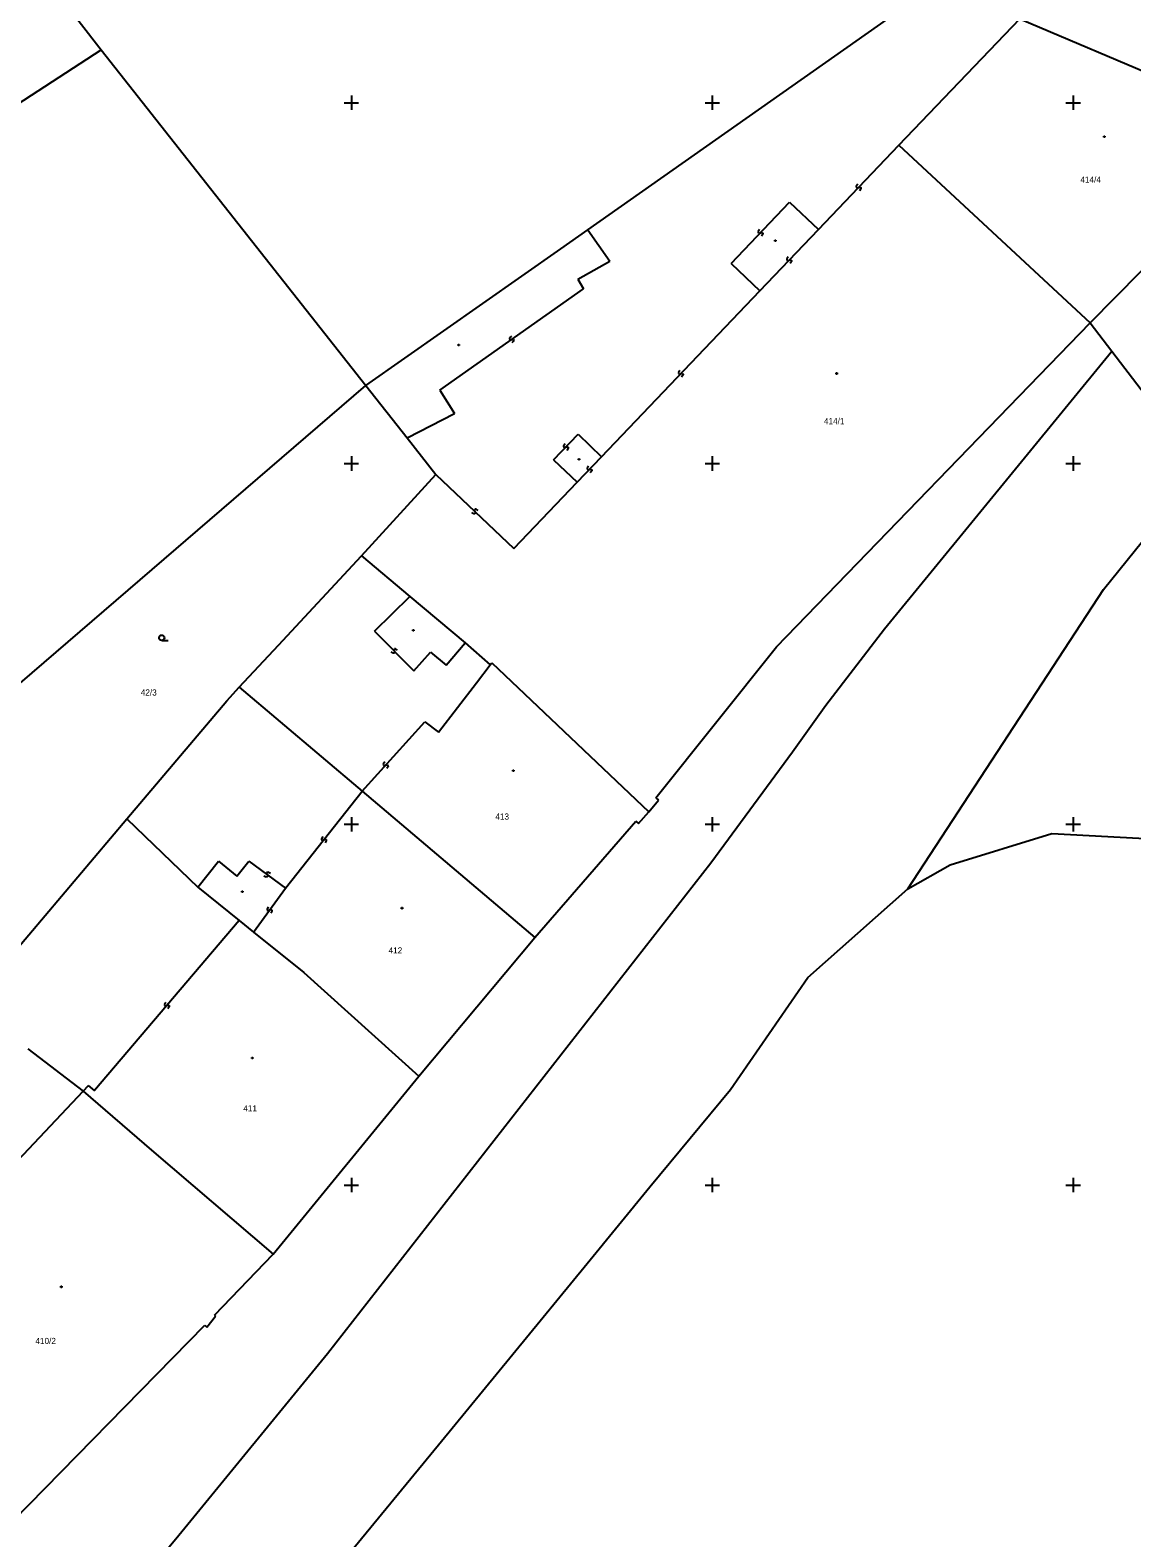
# Model space of a CAD drawing. Extents: x -492811 to -492366, y -1127107 to -1126748.
# Drawn here: x -492657.8 to -492596.7, y -1127059.6 to -1126976 of the extents above; entities that cross this region are included whole.
import ezdxf

# ---------------------------------------------------------------- set-up
doc = ezdxf.new("R2010")
doc.units = 0
doc.layers.add('katastrální mapa', color=7, linetype='Continuous')
doc.layers.add('síť', color=7, linetype='Continuous')

msp = doc.modelspace()

# ---------------------------------------------------------------- linework, layer by layer
at = {"layer": 'katastrální mapa'}
for p, q in [((-492626.9, -1126987.04), (-492604.21, -1126971.08)), ((-492657.67, -1126972.16), (-492653.87, -1126977.07)), ((-492609.66, -1126982.36), (-492602.96, -1126975.34)), ((-492602.96, -1126975.34), (-492592.02, -1126979.99)), ((-492702.2, -1127008.51), (-492653.87, -1126977.07)), ((-492653.87, -1126977.07), (-492639.2, -1126995.68)), ((-492598.3, -1126981.85), (-492598.24, -1126981.85)), ((-492598.3, -1126981.91), (-492598.3, -1126981.85)), ((-492598.24, -1126981.85), (-492598.24, -1126981.91)), ((-492614.12, -1126987.03), (-492609.66, -1126982.36)), ((-492609.66, -1126982.36), (-492599.05, -1126992.2)), ((-492599.05, -1126992.2), (-492589.22, -1126982.18)), ((-492598.24, -1126981.91), (-492598.3, -1126981.91)), ((-492611.94, -1126984.51), (-492612.02, -1126984.63)), ((-492612.02, -1126984.63), (-492612.02, -1126984.68)), ((-492612.02, -1126984.68), (-492611.99, -1126984.71)), ((-492611.99, -1126984.71), (-492611.93, -1126984.71)), ((-492611.93, -1126984.71), (-492611.85, -1126984.68)), ((-492611.85, -1126984.68), (-492611.79, -1126984.68)), ((-492611.76, -1126984.76), (-492611.84, -1126984.88)), ((-492611.79, -1126984.68), (-492611.76, -1126984.71)), ((-492611.76, -1126984.71), (-492611.76, -1126984.76)), ((-492618.95, -1126988.91), (-492615.71, -1126985.51)), ((-492615.71, -1126985.51), (-492614.12, -1126987.03)), ((-492628.4, -1126988.09), (-492626.9, -1126987.04)), ((-492626.9, -1126987.04), (-492625.68, -1126988.78)), ((-492617.38, -1126987.03), (-492617.46, -1126987.14)), ((-492617.46, -1126987.14), (-492617.46, -1126987.2)), ((-492617.46, -1126987.2), (-492617.43, -1126987.23)), ((-492617.43, -1126987.23), (-492617.37, -1126987.23)), ((-492617.37, -1126987.23), (-492617.29, -1126987.19)), ((-492617.36, -1126990.43), (-492614.12, -1126987.03)), ((-492617.29, -1126987.19), (-492617.23, -1126987.19)), ((-492617.2, -1126987.28), (-492617.28, -1126987.39)), ((-492617.23, -1126987.19), (-492617.2, -1126987.22)), ((-492617.2, -1126987.22), (-492617.2, -1126987.28)), ((-492616.53, -1126987.62), (-492616.47, -1126987.62)), ((-492616.53, -1126987.68), (-492616.53, -1126987.62)), ((-492616.47, -1126987.68), (-492616.53, -1126987.68)), ((-492616.47, -1126987.62), (-492616.47, -1126987.68)), ((-492639.2, -1126995.68), (-492628.4, -1126988.09)), ((-492627.45, -1126989.78), (-492625.68, -1126988.78)), ((-492618.95, -1126988.91), (-492617.36, -1126990.43)), ((-492615.79, -1126988.55), (-492615.87, -1126988.66)), ((-492615.87, -1126988.66), (-492615.87, -1126988.72)), ((-492615.87, -1126988.72), (-492615.84, -1126988.75)), ((-492615.84, -1126988.75), (-492615.78, -1126988.75)), ((-492615.78, -1126988.75), (-492615.7, -1126988.71)), ((-492615.7, -1126988.71), (-492615.64, -1126988.71)), ((-492615.61, -1126988.8), (-492615.69, -1126988.91)), ((-492615.64, -1126988.71), (-492615.61, -1126988.74)), ((-492615.61, -1126988.74), (-492615.61, -1126988.8)), ((-492627.45, -1126989.78), (-492627.14, -1126990.32)), ((-492635.1, -1126995.93), (-492627.14, -1126990.32)), ((-492626.13, -1126999.62), (-492617.36, -1126990.43)), ((-492616.44, -1127010.17), (-492599.05, -1126992.2)), ((-492599.05, -1126992.2), (-492597.85, -1126993.77)), ((-492634.09, -1126993.4), (-492634.03, -1126993.4)), ((-492634.09, -1126993.46), (-492634.09, -1126993.4)), ((-492634.03, -1126993.46), (-492634.09, -1126993.46)), ((-492634.03, -1126993.4), (-492634.03, -1126993.46)), ((-492631.23, -1126993.03), (-492631.24, -1126993.09)), ((-492631.24, -1126993.09), (-492631.22, -1126993.12)), ((-492631.13, -1126992.94), (-492631.23, -1126993.03)), ((-492631.22, -1126993.12), (-492631.16, -1126993.13)), ((-492631.16, -1126993.13), (-492631.08, -1126993.12)), ((-492631.01, -1126993.22), (-492631.11, -1126993.31)), ((-492631.08, -1126993.12), (-492631.02, -1126993.13)), ((-492631.02, -1126993.13), (-492631, -1126993.16)), ((-492631, -1126993.16), (-492631.01, -1126993.22)), ((-492610.45, -1127009.17), (-492597.85, -1126993.77)), ((-492597.85, -1126993.77), (-492592.92, -1127000.25)), ((-492621.79, -1126994.84), (-492621.87, -1126994.96)), ((-492621.87, -1126994.96), (-492621.87, -1126995.01)), ((-492621.87, -1126995.01), (-492621.84, -1126995.04)), ((-492621.84, -1126995.04), (-492621.79, -1126995.04)), ((-492621.79, -1126995.04), (-492621.7, -1126995.01)), ((-492621.7, -1126995.01), (-492621.65, -1126995.01)), ((-492621.62, -1126995.09), (-492621.7, -1126995.21)), ((-492621.65, -1126995.01), (-492621.62, -1126995.04)), ((-492621.62, -1126995.04), (-492621.62, -1126995.09)), ((-492613.14, -1126994.98), (-492613.08, -1126994.98)), ((-492613.14, -1126995.04), (-492613.14, -1126994.98)), ((-492613.08, -1126995.04), (-492613.14, -1126995.04)), ((-492613.08, -1126994.98), (-492613.08, -1126995.04)), ((-492670.72, -1127022.8), (-492639.2, -1126995.68)), ((-492639.2, -1126995.68), (-492636.91, -1126998.58)), ((-492635.1, -1126995.93), (-492634.28, -1126997.22)), ((-492636.91, -1126998.58), (-492634.28, -1126997.22)), ((-492628.79, -1126999.79), (-492627.43, -1126998.38)), ((-492627.43, -1126998.38), (-492626.13, -1126999.62)), ((-492636.91, -1126998.58), (-492635.31, -1127000.61)), ((-492628.16, -1126998.9), (-492628.24, -1126999.02)), ((-492628.24, -1126999.02), (-492628.24, -1126999.07)), ((-492628.24, -1126999.07), (-492628.21, -1126999.1)), ((-492628.21, -1126999.1), (-492628.15, -1126999.1)), ((-492628.15, -1126999.1), (-492628.07, -1126999.07)), ((-492628.07, -1126999.07), (-492628.01, -1126999.07)), ((-492627.98, -1126999.15), (-492628.06, -1126999.27)), ((-492628.01, -1126999.07), (-492627.98, -1126999.1)), ((-492627.98, -1126999.1), (-492627.98, -1126999.15)), ((-492628.79, -1126999.79), (-492627.48, -1127001.04)), ((-492627.48, -1127001.04), (-492626.13, -1126999.62)), ((-492627.41, -1126999.74), (-492627.35, -1126999.74)), ((-492627.41, -1126999.8), (-492627.41, -1126999.74)), ((-492627.35, -1126999.8), (-492627.41, -1126999.8)), ((-492627.35, -1126999.74), (-492627.35, -1126999.8)), ((-492626.85, -1127000.15), (-492626.93, -1127000.26)), ((-492639.44, -1127005.11), (-492635.31, -1127000.61)), ((-492635.31, -1127000.61), (-492630.99, -1127004.71)), ((-492630.99, -1127004.71), (-492627.48, -1127001.04)), ((-492626.93, -1127000.26), (-492626.93, -1127000.32)), ((-492626.93, -1127000.32), (-492626.9, -1127000.35)), ((-492626.9, -1127000.35), (-492626.85, -1127000.35)), ((-492626.85, -1127000.35), (-492626.76, -1127000.31)), ((-492626.76, -1127000.31), (-492626.71, -1127000.31)), ((-492626.68, -1127000.4), (-492626.76, -1127000.51)), ((-492626.71, -1127000.31), (-492626.68, -1127000.34)), ((-492626.68, -1127000.34), (-492626.68, -1127000.4)), ((-492598.31, -1127006.99), (-492592.92, -1127000.25)), ((-492633.22, -1127002.79), (-492633.33, -1127002.71)), ((-492633.14, -1127002.53), (-492633.17, -1127002.56)), ((-492633.17, -1127002.56), (-492633.17, -1127002.62)), ((-492633.17, -1127002.62), (-492633.13, -1127002.7)), ((-492633.08, -1127002.53), (-492633.14, -1127002.53)), ((-492633.13, -1127002.7), (-492633.13, -1127002.76)), ((-492632.97, -1127002.61), (-492633.08, -1127002.53)), ((-492633.16, -1127002.79), (-492633.22, -1127002.79)), ((-492633.13, -1127002.76), (-492633.16, -1127002.79)), ((-492644.04, -1127010.07), (-492639.44, -1127005.11)), ((-492639.44, -1127005.11), (-492636.76, -1127007.37)), ((-492638.71, -1127009.29), (-492636.76, -1127007.37)), ((-492636.76, -1127007.37), (-492633.7, -1127009.94)), ((-492609.16, -1127023.57), (-492598.31, -1127006.99)), ((-492638.71, -1127009.29), (-492636.53, -1127011.5)), ((-492636.59, -1127009.22), (-492636.53, -1127009.22)), ((-492636.59, -1127009.28), (-492636.59, -1127009.22)), ((-492636.53, -1127009.28), (-492636.59, -1127009.28)), ((-492636.53, -1127009.22), (-492636.53, -1127009.28)), ((-492613.71, -1127013.4), (-492610.45, -1127009.17)), ((-492650.51, -1127009.81), (-492650.16, -1127009.81)), ((-492646.21, -1127012.4), (-492644.04, -1127010.07)), ((-492637.6, -1127010.27), (-492637.63, -1127010.3)), ((-492637.55, -1127010.27), (-492637.6, -1127010.27)), ((-492637.44, -1127010.35), (-492637.55, -1127010.27)), ((-492634.75, -1127011.18), (-492633.7, -1127009.94)), ((-492633.7, -1127009.94), (-492632.3, -1127011.16)), ((-492623.12, -1127018.53), (-492616.44, -1127010.17)), ((-492637.69, -1127010.52), (-492637.8, -1127010.44)), ((-492637.64, -1127010.52), (-492637.69, -1127010.52)), ((-492637.61, -1127010.49), (-492637.64, -1127010.52)), ((-492637.63, -1127010.3), (-492637.63, -1127010.35)), ((-492637.63, -1127010.35), (-492637.61, -1127010.44)), ((-492637.61, -1127010.44), (-492637.61, -1127010.49)), ((-492636.53, -1127011.5), (-492635.62, -1127010.45)), ((-492635.62, -1127010.45), (-492634.75, -1127011.18)), ((-492632.3, -1127011.16), (-492632.21, -1127011.04)), ((-492632.21, -1127011.04), (-492623.52, -1127019.31)), ((-492633.06, -1127012.15), (-492632.3, -1127011.16)), ((-492646.91, -1127013.15), (-492646.21, -1127012.4)), ((-492646.21, -1127012.4), (-492639.4, -1127018.17)), ((-492635.17, -1127014.89), (-492633.06, -1127012.15)), ((-492652.44, -1127019.69), (-492646.91, -1127013.15)), ((-492615.56, -1127015.98), (-492613.71, -1127013.4)), ((-492636.79, -1127015.28), (-492635.92, -1127014.32)), ((-492635.92, -1127014.32), (-492635.17, -1127014.89)), ((-492639.4, -1127018.17), (-492636.79, -1127015.28)), ((-492620.08, -1127022.13), (-492615.56, -1127015.98)), ((-492638.15, -1127016.54), (-492638.23, -1127016.66)), ((-492638.23, -1127016.66), (-492638.22, -1127016.72)), ((-492638.22, -1127016.72), (-492638.19, -1127016.74)), ((-492638.19, -1127016.74), (-492638.14, -1127016.74)), ((-492638.14, -1127016.74), (-492638.05, -1127016.71)), ((-492638.05, -1127016.71), (-492638, -1127016.71)), ((-492637.96, -1127016.79), (-492638.04, -1127016.91)), ((-492638, -1127016.71), (-492637.97, -1127016.73)), ((-492637.97, -1127016.73), (-492637.96, -1127016.79)), ((-492631.06, -1127017), (-492631, -1127017)), ((-492631.06, -1127017.06), (-492631.06, -1127017)), ((-492631, -1127017.06), (-492631.06, -1127017.06)), ((-492631, -1127017), (-492631, -1127017.06)), ((-492643.65, -1127023.54), (-492639.4, -1127018.17)), ((-492639.4, -1127018.17), (-492629.83, -1127026.28)), ((-492623.12, -1127018.53), (-492622.97, -1127018.67)), ((-492624.08, -1127019.95), (-492623.52, -1127019.31)), ((-492623.52, -1127019.31), (-492622.97, -1127018.67)), ((-492660.97, -1127029.78), (-492652.44, -1127019.69)), ((-492652.44, -1127019.69), (-492648.51, -1127023.48)), ((-492629.83, -1127026.28), (-492624.23, -1127019.82)), ((-492624.23, -1127019.82), (-492624.08, -1127019.95)), ((-492641.59, -1127020.68), (-492641.66, -1127020.8)), ((-492641.66, -1127020.8), (-492641.65, -1127020.86)), ((-492641.65, -1127020.86), (-492641.62, -1127020.88)), ((-492641.62, -1127020.88), (-492641.57, -1127020.87)), ((-492641.57, -1127020.87), (-492641.48, -1127020.84)), ((-492641.48, -1127020.84), (-492641.43, -1127020.83)), ((-492641.39, -1127020.91), (-492641.46, -1127021.03)), ((-492641.43, -1127020.83), (-492641.4, -1127020.85)), ((-492641.4, -1127020.85), (-492641.39, -1127020.91)), ((-492606.81, -1127022.24), (-492601.18, -1127020.51)), ((-492601.18, -1127020.51), (-492595.33, -1127020.82)), ((-492648.51, -1127023.48), (-492647.36, -1127022.05)), ((-492647.36, -1127022.05), (-492646.35, -1127022.87)), ((-492646.35, -1127022.87), (-492645.69, -1127022.05)), ((-492645.69, -1127022.05), (-492643.65, -1127023.54)), ((-492644.68, -1127022.67), (-492644.7, -1127022.7)), ((-492644.7, -1127022.7), (-492644.69, -1127022.76)), ((-492644.69, -1127022.76), (-492644.65, -1127022.83)), ((-492644.62, -1127022.66), (-492644.68, -1127022.67)), ((-492644.49, -1127022.72), (-492644.62, -1127022.66)), ((-492641.33, -1127049.34), (-492620.08, -1127022.13)), ((-492609.16, -1127023.57), (-492606.81, -1127022.24)), ((-492648.51, -1127023.48), (-492646.22, -1127025.33)), ((-492645.42, -1127025.97), (-492643.65, -1127023.54)), ((-492644.72, -1127022.93), (-492644.85, -1127022.87)), ((-492644.66, -1127022.92), (-492644.72, -1127022.93)), ((-492644.64, -1127022.89), (-492644.66, -1127022.92)), ((-492644.65, -1127022.83), (-492644.64, -1127022.89)), ((-492614.71, -1127028.49), (-492609.16, -1127023.57)), ((-492646.07, -1127023.71), (-492646.01, -1127023.71)), ((-492646.07, -1127023.77), (-492646.07, -1127023.71)), ((-492646.01, -1127023.77), (-492646.07, -1127023.77)), ((-492646.01, -1127023.71), (-492646.01, -1127023.77)), ((-492644.61, -1127024.58), (-492644.67, -1127024.7)), ((-492644.67, -1127024.7), (-492644.66, -1127024.76)), ((-492644.66, -1127024.76), (-492644.63, -1127024.78)), ((-492644.63, -1127024.78), (-492644.57, -1127024.78)), ((-492644.57, -1127024.78), (-492644.5, -1127024.73)), ((-492644.5, -1127024.73), (-492644.44, -1127024.73)), ((-492644.4, -1127024.81), (-492644.46, -1127024.93)), ((-492644.44, -1127024.73), (-492644.41, -1127024.75)), ((-492644.41, -1127024.75), (-492644.4, -1127024.81)), ((-492637.22, -1127024.62), (-492637.16, -1127024.62)), ((-492637.22, -1127024.68), (-492637.22, -1127024.62)), ((-492637.16, -1127024.68), (-492637.22, -1127024.68)), ((-492637.16, -1127024.62), (-492637.16, -1127024.68)), ((-492646.22, -1127025.33), (-492645.42, -1127025.97)), ((-492645.42, -1127025.97), (-492642.64, -1127028.21)), ((-492636.26, -1127033.97), (-492629.83, -1127026.28)), ((-492642.64, -1127028.21), (-492636.26, -1127033.97)), ((-492618.99, -1127034.7), (-492614.71, -1127028.49)), ((-492650.29, -1127029.87), (-492650.36, -1127029.98)), ((-492650.36, -1127029.98), (-492650.36, -1127030.04)), ((-492650.36, -1127030.04), (-492650.33, -1127030.07)), ((-492650.33, -1127030.07), (-492650.27, -1127030.06)), ((-492650.27, -1127030.06), (-492650.19, -1127030.03)), ((-492650.19, -1127030.03), (-492650.13, -1127030.02)), ((-492650.1, -1127030.11), (-492650.17, -1127030.22)), ((-492650.13, -1127030.02), (-492650.1, -1127030.05)), ((-492650.1, -1127030.05), (-492650.1, -1127030.11)), ((-492657.93, -1127032.45), (-492654.86, -1127034.8)), ((-492645.52, -1127032.92), (-492645.46, -1127032.92)), ((-492645.52, -1127032.98), (-492645.52, -1127032.92)), ((-492645.46, -1127032.98), (-492645.52, -1127032.98)), ((-492645.46, -1127032.92), (-492645.46, -1127032.98)), ((-492654.86, -1127034.8), (-492654.57, -1127034.48)), ((-492644.34, -1127043.83), (-492636.26, -1127033.97)), ((-492664.88, -1127045.39), (-492654.86, -1127034.8)), ((-492654.86, -1127034.8), (-492651.07, -1127038.06)), ((-492623.45, -1127040.09), (-492618.99, -1127034.7)), ((-492651.07, -1127038.06), (-492644.34, -1127043.83)), ((-492626.94, -1127044.34), (-492623.45, -1127040.09)), ((-492647.59, -1127047.21), (-492644.34, -1127043.83)), ((-492635.17, -1127054.4), (-492626.94, -1127044.34)), ((-492656.1, -1127045.61), (-492656.04, -1127045.61)), ((-492656.1, -1127045.67), (-492656.1, -1127045.61)), ((-492656.04, -1127045.67), (-492656.1, -1127045.67)), ((-492656.04, -1127045.61), (-492656.04, -1127045.67)), ((-492659.65, -1127059.51), (-492648.12, -1127047.76)), ((-492648.12, -1127047.76), (-492648.01, -1127047.87)), ((-492648.01, -1127047.87), (-492647.53, -1127047.26)), ((-492647.59, -1127047.21), (-492647.53, -1127047.26)), ((-492649.57, -1127059.4), (-492641.33, -1127049.34)), ((-492643.43, -1127064.45), (-492635.17, -1127054.4)), ((-492659.57, -1127071.57), (-492649.57, -1127059.4))]:
    msp.add_line(p, q, dxfattribs=at)
msp.add_lwpolyline([(-492646.22, -1127025.33), (-492654.24, -1127034.76), (-492654.57, -1127034.48)], dxfattribs=at)
msp.add_circle((-492650.51, -1127009.66), 0.15, dxfattribs=at)
at = {"layer": 'síť'}
for p, q in [((-492640.4, -1126980), (-492639.6, -1126980)), ((-492640, -1126979.6), (-492640, -1126980.4)), ((-492620.4, -1126980), (-492619.6, -1126980)), ((-492620, -1126979.6), (-492620, -1126980.4)), ((-492600.4, -1126980), (-492599.6, -1126980)), ((-492600, -1126979.6), (-492600, -1126980.4)), ((-492640.4, -1127000), (-492639.6, -1127000)), ((-492640, -1126999.6), (-492640, -1127000.4)), ((-492620.4, -1127000), (-492619.6, -1127000)), ((-492620, -1126999.6), (-492620, -1127000.4)), ((-492600.4, -1127000), (-492599.6, -1127000)), ((-492600, -1126999.6), (-492600, -1127000.4)), ((-492640.4, -1127020), (-492639.6, -1127020)), ((-492640, -1127019.6), (-492640, -1127020.4)), ((-492620.4, -1127020), (-492619.6, -1127020)), ((-492620, -1127019.6), (-492620, -1127020.4)), ((-492600.4, -1127020), (-492599.6, -1127020)), ((-492600, -1127019.6), (-492600, -1127020.4)), ((-492640.4, -1127040), (-492639.6, -1127040)), ((-492640, -1127039.6), (-492640, -1127040.4)), ((-492620.4, -1127040), (-492619.6, -1127040)), ((-492620, -1127039.6), (-492620, -1127040.4)), ((-492600.4, -1127040), (-492599.6, -1127040)), ((-492600, -1127039.6), (-492600, -1127040.4))]:
    msp.add_line(p, q, dxfattribs=at)

# ---------------------------------------------------------------- texts
at = {"layer": 'katastrální mapa'}
for s, p in [('414/4', (-492599.6, -1126984.43)), ('414/1', (-492613.81, -1126997.82)), ('42/3', (-492651.67, -1127012.86)), ('413', (-492632.02, -1127019.74)), ('412', (-492637.94, -1127027.16)), ('411', (-492645.99, -1127035.92)), ('410/2', (-492657.51, -1127048.81))]:
    msp.add_text(s, height=0.34, dxfattribs=at).set_placement(p)

doc.saveas('drawing.dxf')
